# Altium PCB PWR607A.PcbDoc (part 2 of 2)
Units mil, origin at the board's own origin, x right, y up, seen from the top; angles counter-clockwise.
Board outline 5200 x 2850 mil, 4 copper layers (Top Layer, MidLayer1, MidLayer2, Bottom Layer), stack 61.6 mil thick; 153 components, 65 nets, 324 pads, 227 vias.
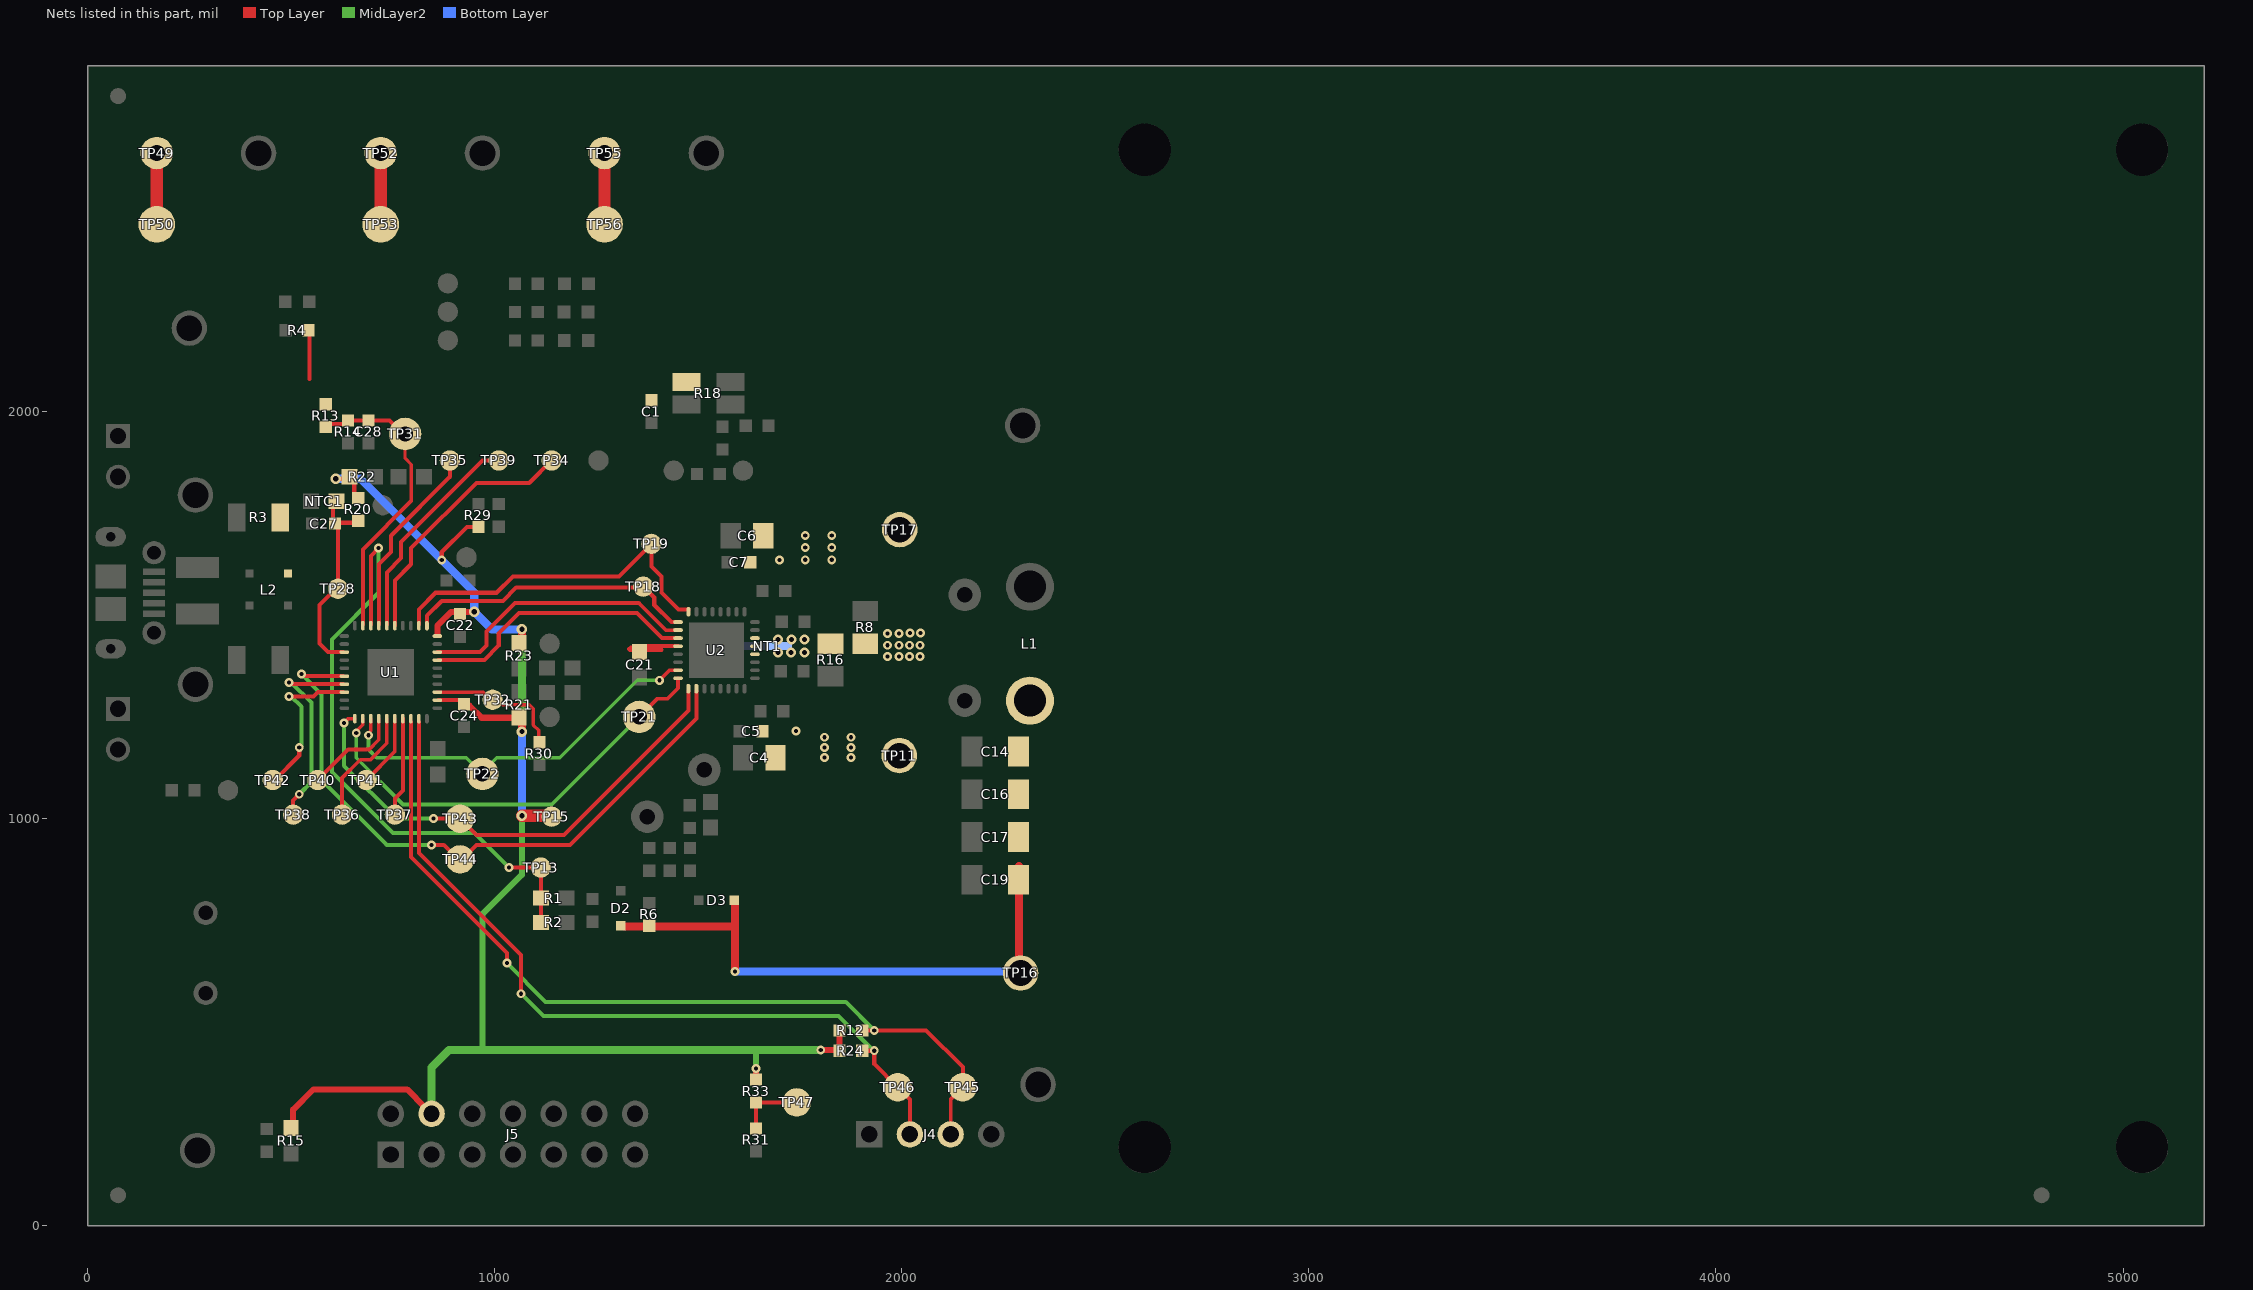
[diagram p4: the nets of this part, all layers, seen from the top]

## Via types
v1: diameter 22, hole 10, Top Layer to Bottom Layer, tented both sides, 140 vias
v2: diameter 22/22/22/22 (per signal layer), hole 10, Top Layer to Bottom Layer, tented both sides, 66 vias
v3: diameter 19.68, hole 7.87, Top Layer to Bottom Layer, 10 vias
v4: diameter 24, hole 12, Top Layer to Bottom Layer, tented both sides, 6 vias
v5: diameter 26, hole 13, Top Layer to Bottom Layer, tented both sides, 5 vias

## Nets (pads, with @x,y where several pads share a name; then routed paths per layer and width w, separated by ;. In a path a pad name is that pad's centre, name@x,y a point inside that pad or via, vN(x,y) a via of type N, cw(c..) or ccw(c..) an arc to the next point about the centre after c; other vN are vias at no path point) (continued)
NetR30_1: R30.1 TP32.1 U1.33 | length 339.6
  Top Layer w8: 1020,1280 1085,1280 1095,1270 1095,1230 1108,1217 R30.1@1108,1175
  Top Layer w9: U1.33@859.17,1310.79 971.21,1310.79 TP32.1@984,1298
  Top Layer w10: TP32.1@995,1292 1003,1292 1010,1285 1015,1285 1020,1280
NetR31_1: R31.1 R33.2 TP47.1 | length 166.8
  Top Layer w9: R33.2@1640,301 R33.2@1642,303 ; R31.1@1642,239 R33.2@1642,303 ; TP47.1@1742,303 R33.2@1642,303
NetTP18_1: TP18.1 U1.1 U2.1 | length 740.3
  Top Layer w10: U1.1@833.58,1477.13 833.58,1498.58 870,1535 1020,1535 1053,1568 TP18.1@1383,1568 ; TP18.1@1365,1570 1392,1543 1392,1525 1434.2,1482.8 U2.1@1450,1482.8 ; TP18.1@1380,1571 TP18.1@1380,1580
NetTP19_1: TP19.1 U1.2 U2.32 | length 887.3
  Top Layer w10: U1.2@813.9,1477.13 813.9,1513.9 855,1555 1005,1555 1045,1595 1305,1595 TP19.1@1385,1675 1385,1620 1410,1595 1410,1556 1451.95,1514.05 U2.32@1475.95,1514.05
NetTP21_1: TP21.1 U1.22 U2.8 | length 1083.4
  Top Layer w9: v1(660,1210) 660,1214.54 676.1,1230.64 U1.22@676.1,1245.83 ; TP21.1@1355,1250 1400,1295 1425,1295 1450.41,1320.41 U2.8@1450.41,1345
  MidLayer2 w9: v1(660,1210) 660,1150 775,1035 1140,1035 TP21.1@1355,1250
NetTP22_1: TP22.1 U1.23 U2.7 | length 971.9
  Top Layer w9: v1(690,1205) 690,1210 695.79,1215.79 U1.23@695.79,1245.83 ; v1(1405,1340) 1429.69,1364.69 U2.7@1450.41,1364.69
  MidLayer2 w9: v1(690,1205) 690,1170 710,1150 930,1150 TP22.1@970,1110 970,1115 1005,1150 1160,1150 1350,1340 v1(1405,1340)
NetTP34_1: TP34.1 U1.5 | length 641.5
  Top Layer w10: U1.5@754.84,1474.17 754.84,1584.84 795,1625 795,1665 955,1825 1085,1825 TP34.1@1140,1880
NetTP35_1: TP35.1 U1.7 | length 472.2
  Top Layer w10: U1.7@715.47,1477.13 715.47,1625.47 745,1655 745,1695 890,1840 890,1870 TP35.1@895,1875
NetTP36_1: TP36.1 U1.25 | length 296.1
  Top Layer w9: 625,1100 670,1145 695,1145 735.16,1185.16 U1.25@735.16,1245.83
  Top Layer w10: TP36.1@625,1010 625,1100
NetTP37_1: TP37.1 U1.27 | length 243.9
  Top Layer w10: TP37.1@755,1010 755,1050 774.53,1069.53 U1.27@774.53,1245.83
NetTP38_1: TP38.1 U1.17 | length 504.1
  Top Layer w10: v1(495,1335) 499.53,1330.47 U1.17@627.87,1330.47 ; TP38.1@505,1010 505,1045 v1(520,1060)
  MidLayer2 w10: v1(495,1335) 500,1335 550,1285 550,1090 v1(520,1060)
NetTP39_1: TP39.1 U1.6 | length 545.1
  Top Layer w10: U1.6@735.16,1477.13 735.16,1605.16 770,1640 770,1680 970,1880 TP39.1@1015,1880
NetTP40_1: TP40.1 U1.24 | length 243.5
  Top Layer w9: TP40.1@565,1095 640,1170 691.88,1170 715.47,1193.59 U1.24@715.47,1245.83
NetTP41_1: TP41.1 U1.26 | length 193.9
  Top Layer w9: TP41.1@685,1095 754.84,1164.84 U1.26@754.84,1245.83
  Top Layer w10: TP41.1@675,1105 TP41.1@685,1115
NetTP42_1: TP42.1 U1.18 | length 382.6
  Top Layer w10: TP42.1@455,1095 460,1095 520,1155 v1(520,1175) ; v1(495,1300) 555,1300 565.79,1310.79 U1.18@627.87,1310.79
  MidLayer2 w10: v1(495,1300) 500,1300 525,1275 v1@525,1180
NetTP43_1: TP43.1 U1.21 U2.9 | length 1227
  Top Layer w9: v1(630,1235) 640.83,1245.83 U1.21@656.42,1245.83
  Top Layer w10: v1(850,1000) TP43.1@915,1000 955,960 1170,960 1475.95,1265.95 U2.9@1475.95,1313.95
  MidLayer2 w10: v1(630,1235) 630,1130 760,1000 v1(850,1000)
NetTP44_1: TP44.1 U1.16 U2.10 | length 1594.3
  Top Layer w10: v1(525,1355) 530,1355 534.84,1350.16 U1.16@627.87,1350.16 ; v1(845,935) 875,935 905,905 925,905 955,935 1185,935 1495.65,1245.65 U2.10@1495.65,1313.95
  MidLayer2 w10: v1(525,1355) 575,1305 575,1095 735,935 v1(845,935)
NetTP49_1: TP49.1 TP50.1 | length 175
  Top Layer w30: TP50.1@170,2460 TP49.1@170,2635
NetTP52_1: TP52.1 TP53.1 | length 175
  Top Layer w30: TP53.1@720,2460 TP52.1@720,2635
NetTP55_1: TP55.1 TP56.1 | length 175
  Top Layer w30: TP56.1@1270,2460 TP55.1@1270,2635
NetU1_37: U1.37 U2.3 | length 673.7
  Top Layer w10: U1.37@862.13,1389.53 974.53,1389.53 1010,1425 1010,1455 1060,1505 1350,1505 1411.5,1443.5 U2.3@1444.9,1443.5
NetU1_38: U1.38 U2.2 | length 689.5
  Top Layer w9: 1354,1530 1420.89,1463.11 U2.2@1450.41,1463.11
  Top Layer w10: U1.38@859.17,1409.21 964.21,1409.21 980,1425 980,1460 1050,1530 1354,1530
PEAK: R1.1 R2.2 TP13.1 U1.8 | length 1529.3
  Top Layer w10: U1.8@695.79,1477.13 695.79,1645.79 v1(715,1665) ; v1(1035,880) TP13.1@1113.5,880 R2.2@1113.5,755
  MidLayer2 w10: v1(715,1665) 715,1555 600,1440 600,1115 750,965 950,965 v1(1035,880)
PGND: C4.2 C5.1 C6.2 C7.1 NT1.2 R8.1 R16.1 TP11.1 TP17.1 U2.20 U2.21 U2.22
  other v1: 1810,1150 1875,1150 1810,1175 1875,1175 1810,1200 1875,1200 1740,1215 1965,1398 1993,1398 2019,1398 2045,1398 1965,1426 1993,1426 2019,1426 2045,1426 1965,1455 1993,1455 2020,1456 2046,1456 1700,1635 1763,1636 1828,1636 1763,1666 1828,1666 1763,1696 1828,1696
  other v4: 1696,1408 1728,1408 1761,1408 1696,1440 1729,1440 1761,1440
SCL: J4.2 R24.1 TP46.1 U1.29 | length 1973
  Top Layer w10: U1.29@813.9,1237.87 813.9,916.1 1065,665 v1(1065,570) ; R24.1@1903,430 v1(1932.5,430) 1932.5,397.5 TP46.1@1990,340 2020,310 J4.2@2020,224.41 J4.2@2017.5,226.91
  MidLayer2 w10: v1(1065,570) 1120,515 1845,515 1928.75,431.25 v1@1933.75,431.25
SDA: J4.3 R12.1 TP45.1 U1.28 | length 2121.9
  Top Layer w9: J4.3@2120,224.41 2120,310 TP45.1@2150,340
  Top Layer w10: U1.28@794.21,1237.87 794.21,905.79 1030,670 v1(1030,645) ; R12.1@1903,480 v1(1932.5,480) 2060,480 2150,390 TP45.1@2150,340
  MidLayer2 w10: v1(1030,645) 1125,550 1862.5,550 v1@1931.25,481.25
TANK: C14.1 C16.1 C17.1 C19.1 D2.2 D3.2 L1.2 R6.2 TP16.1 | length 1393.3
  Top Layer w20: D2.2@1318.69,735 1590,735 ; v1(1590,625) 1590,735 ; D3.2@1590,795 1590,735 ; TP16.1@2288.09,597 C19.1@2288.09,884
  Bottom Layer w20: v1(1590,625) TP16.1@2255,625
TSENSE: C27.2 NTC1.2 R20.2 TP28.1 U1.13 | length 481.7
  Top Layer w10: C27.2@603,1725 605,1727 603,1729 NTC1.2@603,1780 ; U1.13@627.87,1409.21 590.79,1409.21 570,1430 570,1525 605,1560 610,1560 TP28.1@615,1565 615,1727 R20.2@655,1727
VCC_3: C21.1 C22.1 C24.2 J5.4 R12.2 R15.2 R20.1 R21.2 R22.2 R23.2 R24.2 R29.1 R33.1 TP15.1 U1.32 U1.40 U2.4 | length 4310.5
  Top Layer w10: v5(610,1835) 643.5,1835 R22.2@647,1835 ; R20.1@655,1783 R22.2@655,1828 ; U1.32@862.13,1291.1 916.9,1291.1 C24.2@925,1278 ; v1(870,1635) 870,1655 932,1717 R29.1@960,1717 ; 1330,1417 1332,1415 1410,1415 ; 1335,1420 C21.1@1340,1420 ; C21.1@1368.8,1423.8 1415,1423.8 ; U2.4@1444.9,1423.8 1415,1423.8 ; U2.4@1450.41,1423.74 1415.06,1423.74 1415,1423.8
  Top Layer w15: R15.2@505,255.5 505,285 555,335 785,335 830,290 J5.4@845,290 ; U1.40@860,1452 860,1475 893,1508 v5(950,1508) ; C24.2@925,1278 938,1278 968,1248 R21.2@1067,1248 ; TP15.1@1139,1014 1149,1014 1140,1023 TP15.1@1140,1005 ; R33.1@1642,359 v1(1642,386) ; v1(1801,432) 1845,432 R24.2@1847,430 R12.2@1847,480
  Top Layer w20: v5(1067,1214) R21.2@1067,1248 ; R23.2@1067,1430 v5(1067,1465)
  Top Layer w30: v5(1067,1007) 1138,1007 TP15.1@1140,1005
  MidLayer2 w15: 970,432 970,765 1067,862 v5(1067,1007) ; v1(1642,386) 1642,430
  MidLayer2 w20: J5.4@845,290 845,389 888,432 970,432 v1(1801,432) ; v5(1067,1214) v5(1067,1465)
  Bottom Layer w20: v5(610,1835) 670,1835 v1(870,1635) 950,1555 v5(950,1508) ; v5@950.18,1508 v5(950,1508) ; v5(1067,1007) v5(1067,1214) ; v5(1067,1465) 993,1465 v5(950,1508)
VCC_5: C1.2 L2.1 R3.2 R4.2 R13.2 R18.1 | length 115
  Top Layer w10: 545,2080 R4.2@545,2195
VSENSE: C28.1 R13.1 R14.2 TP31.1 U1.9 | length 738.6
  Top Layer w8: TP31.1@780,1945 780,1885 795,1870 795,1780
  Top Layer w10: R13.1@595,1967 598,1970 637,1970 645,1978 C28.1@690,1978 742,1978 770,1950 780,1950 TP31.1@785,1945 ; U1.9@676.1,1477.13 676.1,1661.1 795,1780
  MidLayer2 w10: TP31.1@780,1940 TP31.1@785,1945
pads on no net: FID1.1 FID2.1 FID3.1 H3.0 H6.0 H9.0 H12.0 H17.0 H20.0 J2.2 J2.3 J2.4 J2.6 J2.7 J2.8 J2.9 J2.10 J2.11 J4.4 J5.2 J5.3 J5.5 J5.6 J5.8 J5.10 J5.11 J5.12 J5.13 J5.14

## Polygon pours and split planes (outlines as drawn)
GND on Top Layer "Top Layer-No Net 12" (solid, remove dead copper, pour order 99): -1,2850 0,2849 2561,2849 2561,-1 2558,2 -2,2 -2,2844 4,2850 5,2849 7,2849
PGND on Top Layer "Top Layer-No Net 1" (solid, remove dead copper, pour order 88): 1930,1455 1955,1480 2070,1480 2070,1370 1954,1370 1935,1388.63 1630,1390 1630,1455
NetC10_1 on Top Layer "Top Layer-No Net 10" (solid, remove dead copper, pour order 91): 1937.5,1528.5 1937.5,1508.4 1950,1496.85 1955,1495 2380.29,1495 2380.29,1645 1865,1645 1865,1595 1935,1575 1937,1508.86 1938,1507.93
TANK on Top Layer "Top Layer-No Net 1" (solid, remove dead copper, pour order 92): 2245,815 2380,815 2380,1350 2245,1350
NetC10_1 on Top Layer "Top Layer-No Net 4" (solid, remove dead copper, pour order 87): 1590,1600 1595,1605 1955,1605 1955,1541.3 1938.15,1514 1590,1514
GND on Top Layer "Top-AGND 1" (solid, remove dead copper, pour order 98): 2598,2499 2598,1456.5 2485.5,1456.5 2485.5,1339 2598,1339 2598,314 5125.5,314 5125.5,2499
GND on Top Layer "Top Layer-No Net 8" (solid, remove dead copper, pour order 86): 657,1428.73 657,1270.87 657.1,1270.78 657.1,1270 835,1270 835,1325.86 835,1450 684.47,1450 657.1,1450 657,1449.9 657,1428.73 657,1423.72 657.1,1423.62
NetC2_2 on Top Layer "Top Layer-No Net 7" (solid, remove dead copper, pour order 83): 1640,1180 1620,1200 1620,1334 1570,1334 1570,1070 1640,1070
PGND on Top Layer "Top Layer-No Net 3" (solid, remove dead copper, pour order 85): 1665,1120 1905,1120 1905,1230 1645,1230 1645,1200 1665,1180
VCC_3 on Top Layer "Top Layer-No Net 11" (solid, remove dead copper, pour order 89): 1275,1430 1230,1385 1230,1180 1055,1005 1055,990 1165,990 1300,1125 1300,1180 1300,1340 1350,1390 1375,1390 1395,1410 1405,1410 1498,1412.16 1498,1429
NetC10_1 on Top Layer "Top Layer-No Net 5" (solid, remove dead copper, pour order 82): 1626,1459 1626,1534 1627,1535 1735,1535 1740,1515 1720,1495 1720,1460 1625,1460 1625,1462
NetC14_2 on Top Layer "Top Layer-No Net 2" (solid, remove dead copper, pour order 94): 1625,1293.17 1635.04,1283.54 1650.16,1269.05 1680.7,1269.05 1680.7,1230.41 2114.19,1230.41 2154.51,1191.77 2154.51,815 2215,815 2215,1293.21 2150,1355 1865,1355 1625,1346
NetC14_2 on Top Layer "Top Layer-No Net" (solid, remove dead copper, pour order 90): 1625,1343.95 1672,1296.95 1672,1240 1709.8,1240 1710,1240.2 2215,1240.2 2215,1306 2170,1350 2165,1355 1860,1355 1735,1345 1720,1360 1720,1380 1665,1380 1655,1390 1625,1390
PGND on Top Layer "Top Layer-No Net 1" (solid, remove dead copper, pour order 84): 1635,1725 1855,1725 1855,1622.5 1849.86,1615 1634,1615
NetC2_2 on Top Layer "Top Layer-No Net 9" (solid, remove dead copper, pour order 93): 1545,2050 1625,2050 1640,2035 1640,1820 1550,1820 1550,1505 1580,1505 1580,1605 1595,1620 1595,1655 1610,1670 1610,1725 1630,1745 1795,1745 1810,1760 1810,2035 1730,2115 1545,2115
VCC_5 on Top Layer "Top Layer-No Net 6" (solid, remove dead copper, pour order 97): 415,1730 415,2005 525,2115 1505,2115 1505,2005 575,2005 520,1950 520,1580 460,1580 460,1685
NetC8_1 on Top Layer "Top Layer-No Net 13" (solid, remove dead copper, pour order 96): 127,1598 105,1620 105,1710 85,1730 55,1730 30,1755 30,1985 185,1985 330,1840 330,1775 390,1775 390,1715 430,1675 430,1580 220,1580 202,1598
NetC8_2 on Top Layer "Top Layer-No Net 14" (solid, remove dead copper, pour order 95): 200,1512 235,1545 429.7,1544.99 430,1445 390,1405 390,1355 355,1355 125,1125 30,1125 30,1355 55,1380 90,1380 110,1400 110,1495 127,1512
PGND on MidLayer2 "MidLayer2-No Net" (solid, remove dead copper, pour order 102): 1680,1680 1755,1755 2050,1755 2050,1655 2000,1655 1952.5,1607.5 1952.5,1537.5 2015,1475 2070,1475 2070,1110 1820,1110 1680,1250
NetC2_2 on MidLayer2 "Top Layer-No Net 1" (solid, remove dead copper, pour order 101): 1730,2100 1640,2100 1640,1900 1620,1880 1620,1195 1570,1145 1570,1070 1650,1070 1650,1125 1670,1145 1670,1700 1745,1775 1745,2085
GND on Bottom Layer "Bottom-AGND 1" (solid, remove dead copper, pour order 104): 2598.25,2499 2598.25,314 5125.75,314 5125.75,2499
PGND on Bottom Layer "MidLayer2-No Net" (solid, remove dead copper, pour order 103): 1680,1680 1755,1755 2050,1755 2050,1655 2000,1655 1952.5,1607.5 1952.5,1537.5 2015,1475 2070,1475 2070,1110 1820,1110 1680,1250
GND on Bottom Layer "Bottom Layer-No Net" (solid, remove dead copper, pour order 105): 1,2846 5,2850 2563,2850 2563,0 2560,-3 0,-3 6,3 6,2850 18,2850
GND on MidLayer1 "MidLayer1-No Net" (solid, remove dead copper, pour order 100): -1,2846 2562,2846 2562,-2 1,-2 0,-1 0,2846 6,2846

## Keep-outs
Keep-Out Layer:
  lines w8: -4,0 ccw(c0,0) 0,-4 ; -4,0 ccw(c0,0) 0,-4 ; -4,0 -4,2850 ; -4,2850 cw(c0,2850) 0,2854 ; -4,2850 cw(c0,2850) 0,2854 ; 0,-4 5200,-4 ; 0,2854 5200,2854 ; 5200,-4 ccw(c5200,0) 5204,0 ; 5200,-4 ccw(c5200,0) 5204,0 ; 5200,2854 cw(c5200,2850) 5204,2850 ; 5200,2854 cw(c5200,2850) 5204,2850 ; 5204,0 5204,2850
  text ".Layer_Name" at 577,-858.49 h60

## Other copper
Top Layer:
  rectangle net GND: 1407,1382 1450.41,1401
  rectangle net GND: 885,1425 959.61,1475
  rectangle net NetC14_2: 2073,815 2215,1248
  rectangle net GND: 849,1210 898,1275
  rectangle net NetC14_2: 1625,1345 1655,1390
  pour cut-out: 1478.99,1488.94 1474.89,1488.94 1473.89,1487.94 1473.89,1424 1478.99,1424
  pour cut-out: 1618.08,1342.18 1618.08,1346.28 1617.08,1347.28 1468.58,1347.28 1468.58,1342.28
  pour cut-out: 1619.5,1479.9 1619.5,1484 1618.5,1485 1470,1485 1470,1480
  pour cut-out: 470,1575 470.59,1565.13 445,1565 445,1545 419.41,1544.99 420,1575
  pour cut-out: 845,2355 1240,2355 1240,2130 845,2130
  pour cut-out: 2135,1495.2 2395,1495.2 2395,1400 2395,1380 2398,1374 2390,1360 2240,1360 2240,1375 2135,1375
  pour cut-out: 1610.39,772.5 1615.45,772.5 1615.45,617.2 1608.84,617.2 1608.84,770.95
  pour cut-out: 1273.19,714.19 1273,714 1566,714 1566,614 1574,614 1576,616 1575,617 1575,728 1274.89,728 1273.19,726.3
  pour cut-out: 2308.48,795 2308.48,671.52 2313,667 2320,667 2320,795
  pour cut-out: 2054.5,795 2256.5,795 2256.5,708 2256.5,652 2261.5,652 2276.5,667 2276.5,815 2073.5,815 2073.5,1215 2054.5,1215
  pour cut-out: 2386,1373 2387,1374 2398,1374 2400,815 2400,795 2310,795 2310,815 2386,815 2387.21,1373.21 2388,1374
  pour cut-out: 2212,806.8 2256.8,806.8 2258,808 2256,810 2256,815 2214,815 2211,812 2212,811
  pour cut-out: 831.21,1448.4 829.79,1446.98 829.79,1265.08 832.38,1265.08 835.21,1267.91 835.21,1448.49 831.21,1448.49
  pour cut-out: 656,1445.1 656.1,1445 833.9,1445 833.9,1449.1 832.9,1450.1 655.9,1450.1 655.9,1445.42 656,1445.32
  pour cut-out: 664.13,1270.63 664.13,1450.63 658.04,1450.63 658.04,1271.63 659.04,1270.63 664.13,1270.63 664.13,1271.41 664.04,1271.5
  pour cut-out: 657.19,1275 832.81,1275 833.68,1274.13 833.68,1270.81 833.09,1270.22 657.09,1270.22 657.09,1274.9
  pour cut-out: 1585,910 1585,812.5 1575,812.5 1575,837.5 1575,910
  pour cut-out: 1332.5,845 1357.5,845 1357.5,835 1332.5,835
  pour cut-out: 1140,775 1285,775 1285,765 1140,765
  pour cut-out: 339.14,1850 410,1850 410,1830 340,1830
  pour cut-out: 1505,2130.29 1545,2130.29 1545,2115 1505,2115
  pour cut-out: 1478.99,1364.94 1474.89,1364.94 1473.89,1363.94 1473.89,1300 1478.99,1300
  text ".Layer_Name" at 577,-858.49 h60
MidLayer1:
  text ".Layer_Name" at 577,-858.49 h60
MidLayer2:
  text ".Layer_Name" at 577,-858.49 h60
Bottom Layer:
  rectangle net PGND: 1685,1395 1775,1450
  rectangle net GND: 1595,1399.13 1655,1435
  pour cut-out: 1590,598 2239,598 2242,601 2235,608 1590,608
  pour cut-out: 1590,652 2246,652 2247,651 2241,645 2241,639 1590,639
  text ".Layer_Name" at 577,-858.49 h60

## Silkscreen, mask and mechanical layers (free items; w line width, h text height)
Top Overlay:
  lines w10: 25,2070 285,2070 365,1990 365,1915 365,1790
  lines w40: 2809.5,350.5 2809.5,2450.5 4909.5,2450.5 4909.5,350.5 2809.5,350.5
  text "2015" at 1605,2530 h60
  text "bq50002EVM-607" at 1668,2430 h100
  text "PWR607  Rev. A" at 1780,2346 h60
  text "V_SENSE" at 745,2005 h50
  text "+5V" at 150,1965 h80
  text "VIN" at 160,1895 h80
  text "CS+" at 1325,1797 h50
  text "CS-" at 1655,1796 h50
  text "PWM2" at 1235,1610 h50
  text "/U-D" at 1375,1610 h50
  text "I_SENSE" at 1040,1600 h50
  text "SW1" at 2015,1535 h50
  text "T_SENSE" at 650,1520 h50
  text "PWM1" at 1190,1505 h50
  text "/CLK" at 1325,1505 h50
  text "FOD_THR" at 1083,1468 h50
  text "SW2" at 2010,1275 h50
  text "LED" at 1185,1195 h50
  text "GND" at 145,1190 h80
  text "_" at 200,1170 h90
  text "DMN2" at 1430,1170 h50
  text "DMO1" at 1272,1124 h50
  text "DMO2" at 990,1025 h50
  text "DMN1" at 1204,975 h50
  text "BUZZ" at 285,965 h50
  text "BP3" at 1020,940 h50
  text "PEAK" at 1145,845 h50
  text "TANK" at 2085,585 h50
  text ".Layer_Name" at 577,-858.49 h60
Bottom Overlay:
  text ".Layer_Name" at 577,-858.49 h60
Top Paste:
  text ".Layer_Name" at 577,-858.49 h60
Bottom Paste:
  text ".Layer_Name" at 577,-858.49 h60
Top Solder:
  rectangle: 2595,310 4945,2500
  text ".Layer_Name" at 577,-858.49 h60
  text ".Layer_Name" at 577,-858.49 h60
Bottom Solder:
  text ".Layer_Name" at 577,-858.49 h60
Drill Guide:
  text ".Layer_Name" at 577,-858.49 h60
M1 Board Outline:
  the board outline again, w10
  text ".Layer_Name" at 577,-858.49 h60
M2 Board Dimensions:
  rectangle: -0.5,-285.5 124.5,-160.5
  rectangle: 124.5,-410.5 499.5,-285.5
  lines w7: -0.5,-285.5 999.5,-285.5 ; 124.5,-410.5 124.5,-160.5 ; 249.5,-410.5 249.5,-160.5 ; 499.5,-410.5 499.5,-160.5 ; 749.5,-410.5 749.5,-160.5 ; -0.5,-410.5 999.5,-410.5 999.5,-160.5 -0.5,-160.5 -0.5,-410.5
  lines w10: -0.5,-475.5 -0.5,-455.5 ; 59.5,-485.5 -0.5,-465.5 ; 59.5,-445.5 -0.5,-465.5 ; 223.58,-465.5 -0.5,-465.5 ; 775.42,-465.5 999.5,-465.5 ; 939.5,-485.5 999.5,-465.5 ; 939.5,-445.5 999.5,-465.5 ; 999.5,-475.5 999.5,-455.5
  text "1000 (mil)" at 233.58,-501.49 h60
  text ".Layer_Name" at 577,-858.49 h60
M3 3D STEP Top:
  text ".Layer_Name" at 577,-858.49 h60
M4 3D STEP Bottom:
  text ".Layer_Name" at 577,-858.49 h60
M5 Assembly Top:
  lines w7: 5334,145.5 6459,145.5 ; 5334,268 6456.5,268 ; 5649,25.5 5649,388 ; 6034,25.5 5334,25.5 ; 6034,388 5334,388 ; 5334,25.5 6459,25.5 6459,388 5334,388 ; 5334,25.5 5334,388
  lines w10: -292,-930.17 6308,-930.17 ; -292,-726.83 6310,-726.83 ; -292,-523.5 -292,-1133.5 3713,-1133.5 6310,-1133.5 6310,-523.5 -291.5,-523.5 -291.5,-1133.5 1284,-1133.5 ; 2173,-1133.5 2173,-523.5 ; 3440,-726.83 3440,-523.5 ; 4280,-726.83 4280,-523.5 ; 4902,-1140 4902,-937.17
  text "TABLE 1" at 5721.5,423 h40
  text "Variant" at 5359,313 h40
  text "Label text" at 5794,313 h40
  text "001" at 5426.5,193 h40
  text "bq50002 + bq500511" at 5704,190.5 h40
  text "COMPONENTS MARKED 'DNP' SHOULD NOT BE POPULATED." at 1153.5,-318.5 h60
  text "ASSEMBLY VARIANT:" at 1153,-434 h60
  text ".VariantName" at 2189,-434 h60
  text "PCB VIEWED FROM TOP SIDE" at -228.5,-655.67 h60
  text "BOARD #:" at 2248,-655.67 h60
  text ".PRJ_Number" at 2793.5,-655.67 h60
  text "REV:" at 3638,-655.67 h60
  text ".PCB_Rev" at 3929.5,-655.67 h60
  text "SVN REV:" at 4476,-655.67 h60
  text ".VersionControl_RevNumber" at 4982,-655.67 h60
  text "IGNORE ->" at -228.5,-858.49 h60
  text "PLOT NAME =" at -228.5,-1064.34 h60
  text ".plot_File_Name" at 577,-1064.34 h60
  text "GENERATED    :" at 2250,-1064.34 h60
  text ".Print_Date" at 3119.5,-1064.34 h60
  text ".Print_Time" at 3848.5,-1064.34 h60
  text "TEXAS INSTRUMENTS" at 5113,-1064.34 h60
M6 Assembly Bottom:
  lines w10: -292.5,-727.33 6309.5,-727.33 ; -290.5,-930.67 6309.5,-930.67 ; 1115.5,-1140.5 1115.5,-937.67 ; 1737.5,-727.33 1737.5,-524 ; 2577.5,-727.33 2577.5,-524 ; 3844.5,-1134 3844.5,-524 ; 4733.5,-1134 6309,-1134 6309,-524 -292.5,-524 -292.5,-1134 2304.5,-1134 6309.5,-1134 6309.5,-524
  text "COMPONENTS MARKED 'DNP' SHOULD NOT BE POPULATED." at 6102,-318 h60
  text ".VariantName" at 5058,-434 h60
  text "ASSEMBLY VARIANT:" at 6097,-434 h60
  text ".VersionControl_RevNumber" at 1035.5,-656.17 h60
  text "SVN REV:" at 1541.5,-656.17 h60
  text ".PCB_Rev" at 2088,-656.17 h60
  text "REV:" at 2379.5,-656.17 h60
  text ".PRJ_Number" at 3224,-656.17 h60
  text "BOARD #:" at 3769.5,-656.17 h60
  text "PCB VIEWED FROM BOTTOM SIDE" at 6246,-656.17 h60
  text "IGNORE ->" at 2547.85,-858.49 h60
  text "TEXAS INSTRUMENTS" at 904.5,-1064.84 h60
  text ".Print_Time" at 2169,-1064.84 h60
  text ".Print_Date" at 2898,-1064.84 h60
  text "GENERATED    :" at 3767.5,-1064.84 h60
  text ".plot_File_Name" at 5440.5,-1064.84 h60
  text "PLOT NAME =" at 6246,-1064.84 h60
M9 Title Sheet:
  drawing of 57 lines, arcs and shapes, not listed
  text "1" at 739.84,8036.5 h60
  text "2" at 3235.5,8036.5 h60
  text "3" at 5724.84,8036.5 h60
  text "4" at 8231.51,8036.5 h60
  text "5" at 10730.5,8036.5 h60
  text "6" at 13235.5,8036.5 h60
  text "A" at -416.5,6893.5 h60
  text "A" at 14383.5,6893.5 h60
  text "B" at -416.5,4513.5 h60
  text "B" at 14383.5,4513.5 h60
  text "C" at -416.5,2138.5 h60
  text "C" at 14383.5,2138.5 h60
  text "PROJECT TITLE:" at 11343.5,277.5 h60
  text ".PRJ_Title" at 11393.5,144.17 h60
  text "DESIGNED FOR:" at 11343.5,-23.5 h60
  text ".PRJ_Customer" at 11393.5,-163.5 h60
  text "D" at -416.5,-231.5 h60
  text "D" at 14383.5,-231.5 h60
  text "FILE NAME:" at 11343.5,-323.5 h60
  text ".PCB_File_Name_No_Path" at 11393.5,-443.5 h60
  text "Texas Instruments (TI) and/or its licensors do not warrant the accuracy or completeness of this specification" at 6374,-605.34 h40
  text "ENGINEER:" at 11343.5,-613.5 h60
  text "LAYOUT BY:" at 12848.5,-613.5 h60
  text "or any information contained therein. TI and/or its licensors do not warrant that this design will meet" at 6329.01,-718 h40
  text ".PRJ_Engineer" at 11393.5,-768.49 h60
  text ".PCB_Layout" at 12899,-768.49 h60
  text "the specifications, will be suitable for your application or fit for any particular purpose, or will operate in" at 6329.01,-830.67 h40
  text ".Layer_Name" at 577,-858.49 h60
  text "ALTIUM DESIGNER VERSION:" at 12848.5,-923.5 h60
  text "an implementation. TI and/or its licensors do not warrant that the design is production worthy. You should" at 6329.01,-943.33 h40
  text "completely validate and test your design implementation to confirm the system functionality for your application." at 6374,-1056 h40
  text ".print_Scale" at 11393.5,-1056.83 h60
  text ".Application_BuildNumber" at 12899,-1056.83 h60
  text "1" at 739.84,-1263.5 h60
  text "2" at 3235.5,-1263.5 h60
  text "3" at 5724.84,-1263.5 h60
  text "4" at 8231.51,-1263.5 h60
  text "5" at 10730.5,-1263.5 h60
  text "6" at 13235.5,-1263.5 h60
M10 Fab Notes:
  drawing of 212 lines, arcs and shapes, not listed
  text "DESIGN INFORMATION" at 12381.02,6810 h60
  text "(REFER ALSO ARRAY/PANEL PROFILING INFORMATION)" at 12019.46,6648.29 h60
  text "BOARD SIZE" at 11333.46,6644 h60
  text "2850MIL" at 11795.78,6516.18 h60
  text "X" at 12301.46,6516.18 h60
  text "5200MIL" at 12532.78,6516.18 h60
  text "Number of Layers :" at 11736.46,6319 h60
  text "4" at 12831.27,6309 h60
  text "MIN. TRACK WIDTH:" at 11736.46,6180 h60
  text "8" at 12832.7,6180 h60
  text "MIL" at 12987.46,6180 h60
  text "MIN. CLEARANCE:" at 11736.46,6048 h60
  text "8" at 12832.7,6048 h60
  text "MIL" at 12987.46,6048 h60
  text "MIN. VIA PAD SIZE:" at 11736.46,5916 h60
  text "20" at 12802.71,5916 h60
  text "MIL" at 12987.46,5916 h60
  text "0.15mm (6MIL)" at 12431.46,5774.29 h60
  text "MINIMUM ANNULAR RING" at 11407.23,5770 h60
  text "EXTERNAL" at 13139.46,5770 h60
  text "PER" at 11607.23,5652 h60
  text "IPC-D-275 CLASS 2 LEVEL C" at 11827.23,5652 h60
  text "MIL, HOLES" at 13315.46,5539.71 h60
  text "+/-" at 12923,5539 h60
  text "+/-" at 13777,5539 h60
  text "REGISTRATION TOLERANCES:" at 11407.23,5534 h60
  text "METAL" at 12607,5534 h60
  text "5" at 13183.2,5534 h60
  text "3" at 14016.2,5534 h60
  text "MIL" at 14132.46,5534 h60
  text "MATERIAL:" at 11332.46,5324.54 h60
  text "FR-4 High Tg" at 12318.9,5184.21 h60
  text "FR-408" at 11753.46,5175.64 h60
  text "X" at 12165.46,5175.64 h60
  text "OTHER" at 13241.46,5175.64 h60
  text "62 MIL (1.6mm) +/-10%" at 12073.56,5012.92 h60
  text "THICKNESS:" at 11407.23,5008.64 h60
  text "X" at 11945.4,5008.64 h60
  text "OTHER" at 13358.46,5008.64 h60
  text "TOLERANCE:" at 11407.23,4850.64 h60
  text "X" at 12246.53,4850.64 h60
  text "ANSI IPC-6012 TYPE 3 CLASS 2" at 12433.48,4850.64 h60
  text "OTHER +/-" at 12433.46,4694.64 h60
  text "BOW & TWIST:" at 11407.23,4537.64 h60
  text "X" at 12246.53,4537.64 h60
  text "ANSI IPC-6012 TYPE 3 CLASS 2" at 12433.48,4537.64 h60
  text "OTHER +/-" at 12433.46,4379.13 h60
  text "COPPER THICKNESS (FINISHED):" at 11332.46,4243.64 h60
  text "1.4MIL (1oz)" at 12212.46,4090.92 h60
  text "2MIL (1.4oz)" at 12979.46,4090.92 h60
  text "2.8MIL (2oz)" at 13706.46,4090.92 h60
  text "OUTER:" at 11689.46,4086.64 h60
  text "X" at 12084,4086 h60
  text "1.4MIL (1oz)" at 12212.46,3933.92 h60
  text "2.8MIL (2oz)" at 12979.46,3933.92 h60
  text "N/A" at 13706,3934.29 h60
  text "INNER SIGNAL:" at 11400.38,3929.64 h60
  text "X" at 12085.42,3929.64 h60
  text "DRILLING:" at 11332.46,3790.64 h60
  text "REFERENCE:" at 11407.23,3673.64 h60
  text "X" at 12055.46,3673.64 h60
  text "AS SHOWN" at 12242.46,3673.64 h60
  text "X" at 12956.46,3673.64 h60
  text "NC_DRILL FILES" at 13093.46,3673.64 h60
  text "PTH MIN COPPER THICKNESS:" at 11407.23,3515.64 h60
  text "X" at 12757.46,3515.64 h60
  text "1MIL" at 12894.46,3515.64 h60
  text "OTHER" at 13391.46,3515.64 h60
  text "BOARD FINISH:" at 11332.46,3356.64 h60
  text "SILKSCREEN:" at 11487.68,3238.64 h60
  text "X" at 12436.46,3238.64 h60
  text "TOP" at 12562.46,3238.64 h60
  text "BOTTOM" at 13073.46,3238.64 h60
  text "SILKSCREEN COLOR:" at 11487.68,3071.64 h60
  text "X" at 12435.42,3071.64 h60
  text "WHITE" at 12562.46,3071.64 h60
  text "OTHER" at 13073.46,3071.64 h60
  text "SOLDER RESIST COLOR:" at 11487.68,2901.64 h60
  text "X" at 12055.42,2742.44 h60
  text "GREEN" at 12182.46,2742.44 h60
  text "BLUE" at 12773.46,2742.44 h60
  text "OTHER" at 13311.46,2742.44 h60
  text "IMMERSION GOLD (ENIG)" at 12393.46,2553.92 h60
  text "ENEPIG" at 13731,2550.64 h60
  text "SURFACE FINISH:" at 11332.46,2549.64 h60
  text "X" at 12205,2545 h60
  text "IMM. TIN/SILVER OR EQUIV" at 11662,2392.64 h60
  text "OTHER" at 13093.46,2392.64 h60
  text "ARRAY/PANEL:" at 11332.46,2213.64 h60
  text "CUT AND TRIM PER MECH LAYER 1" at 12393.46,2209.35 h60
  text "N.C. ROUTE" at 12393.46,2057.64 h60
  text "X" at 13072.46,2057.64 h60
  text "V. SCORE" at 13259.46,2057.64 h60
  text "CERTIFICATION:" at 11332.46,1920.64 h60
  text "MATERIALS AND WORKMANSHIP FOR ALL PCBS" at 12057.46,1920.64 h60
  text "TO MEET OR EXCEED THE REQUIREMENTS OF:" at 12057.46,1822.64 h60
  text "X" at 11683.96,1686.13 h60
  text "ANSI IPC-A-600F CLASS ->" at 11822.96,1686.13 h60
  text "X" at 13462.02,1686.13 h60
  text "2" at 13580.96,1686.14 h60
  text "1" at 13265.96,1684.64 h60
  text "3" at 13934.96,1684.64 h60
  text "X" at 11686.02,1526.64 h60
  text "UL 94V-0" at 11822.96,1526.64 h60
  text "X" at 12498.02,1526.64 h60
  text "RoHS" at 12634.96,1526.64 h60
  text "OTHER" at 13279.36,1526.64 h60
  text "PER ORDER" at 13676.42,1526.64 h60
  text "ADDITIONAL REQUIREMENTS:" at 11332.46,1385.64 h60
  text "MICROSECTION:" at 11407.23,1270.64 h60
  text "YES" at 12312.96,1270.64 h60
  text "REQUIRED" at 13174.46,1114.49 h60
  text "BARE BOARD ELEC. TEST:" at 11407.23,1111.64 h60
  text "NONE" at 12712.96,1111.64 h60
  text "X" at 13047.46,1111.64 h60
  text "PER ORDER" at 13766.46,1111.64 h60
  text "MANUFACTURER'S UL:" at 11407.23,954.64 h60
  text "RAIL" at 12572.96,950.35 h60
  text "METAL" at 13064.77,950.35 h60
  text "X" at 13440,950 h60
  text "SILK" at 13576.46,950.35 h60
  text ".Layer_Name" at 577,-858.49 h60
M11 Gerber Information:
  lines w10: -292,-930.17 6308,-930.17 ; -292,-726.83 6310,-726.83 ; -292,-523.5 -292,-1133.5 3713,-1133.5 6310,-1133.5 6310,-523.5 -291.5,-523.5 -291.5,-1133.5 1284,-1133.5 ; 2173,-1133.5 2173,-523.5 ; 3440,-726.83 3440,-523.5 ; 4280,-726.83 4280,-523.5 ; 4902,-1140 4902,-937.17
  text "ALL ARTWORK VIEWED FROM TOP SIDE" at -228.5,-655.67 h60
  text "BOARD #:" at 2248,-655.67 h60
  text ".PRJ_Number" at 2793.5,-655.67 h60
  text "REV:" at 3638,-655.67 h60
  text ".PCB_Rev" at 3929.5,-655.67 h60
  text "SVN REV:" at 4476,-655.67 h60
  text ".VersionControl_RevNumber" at 4982,-655.67 h60
  text "LAYER NAME =" at -228.5,-858.49 h60
  text "PLOT NAME =" at -228.5,-1064.34 h60
  text ".plot_File_Name" at 577,-1064.34 h60
  text "GENERATED    :" at 2250,-1064.34 h60
  text ".Print_Date" at 3119.5,-1064.34 h60
  text ".Print_Time" at 3848.5,-1064.34 h60
  text "TEXAS INSTRUMENTS" at 5113,-1064.34 h60
M12 Stackup:
  lines w6: 11360,7693 14180,7693 ; 11360,7805.6 14180,7805.6 ; 11300,6976 ccw(c11336,6976) 11336,6940 14204,6940 ccw(c14204,6976) 14240,6976 14240,7904 ccw(c14204,7904) 14204,7940 11336,7940 ccw(c11336,7904) 11300,7904 11300,6976
  text "Layer Stack Up Detail for: PWR607A.PcbDoc" at 11360,7835 h51
  text "Layer" at 11360,7763.6 h26
  text "Gerber" at 12347.8,7763.6 h26
  text "Copper" at 12989.85,7763.6 h26
  text "Dielectric" at 13674.35,7763.6 h26
  text "Name" at 11360,7711.6 h26
  text "Document" at 12347.8,7711.6 h26
  text "Thickness" at 12989.85,7711.6 h26
  text "Material" at 13674.35,7711.6 h26
  text "Top Solder Mask" at 11360,7637.92 h36
  text "(.GTS)" at 12347.8,7637.92 h36
  text "Solder Resist" at 13674.35,7637.92 h36
  text "Top Layer" at 11360,7533.75 h36
  text "(.GTL)" at 12347.8,7533.75 h36
  text "1.4mil" at 12989.85,7533.75 h36
  text "FR-4 High Tg" at 13674.35,7481.67 h36
  text "MidLayer1" at 11360,7429.58 h36
  text "(.G1)" at 12347.8,7429.58 h36
  text "1.4mil" at 12989.85,7429.58 h36
  text "FR-4 High Tg" at 13674.35,7377.5 h36
  text "MidLayer2" at 11360,7325.42 h36
  text "(.G2)" at 12347.8,7325.42 h36
  text "1.4mil" at 12989.85,7325.42 h36
  text "FR-4 High Tg" at 13674.35,7273.33 h36
  text "Bottom Layer" at 11360,7221.25 h36
  text "(.GBL)" at 12347.8,7221.25 h36
  text "1.4mil" at 12989.85,7221.25 h36
  text "Bottom Solder Mask" at 11360,7117.08 h36
  text "(.GBS)" at 12347.8,7117.08 h36
  text "Solder Resist" at 13674.35,7117.08 h36
  text ".Layer_Name" at 577,-858.49 h60
M13 Component Bodies Top:
  text ".Layer_Name" at 577,-858.49 h60
M14 Component Bodies Bottom:
  text ".Layer_Name" at 577,-858.49 h60
M15 Courtyards Top:
  text ".Layer_Name" at 577,-858.49 h60
M16 Courtyards Bottom:
  text ".Layer_Name" at 577,-858.49 h60
Drill Drawing:
  text ".legend" at 5350,930 h60
  text "Drill Table" at 5355,720 h60
  text ".Layer_Name" at 577,-858.49 h60

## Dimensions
0,0 to 0,2850 on M2 Board Dimensions
0,0 to 5200,0 on M2 Board Dimensions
